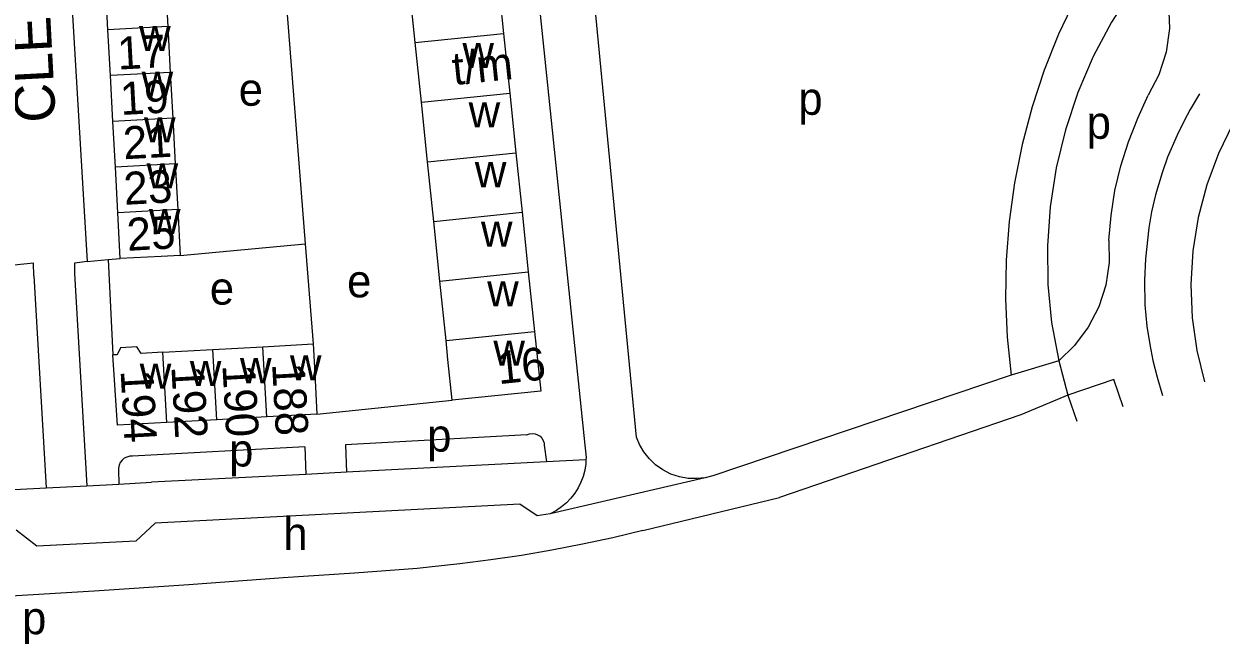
# Model space of a CAD drawing. Extents: x 161258 to 163262, y 380749 to 382054.
# Drawn here: x 162490.8 to 162637.4, y 380751.4 to 380827.3 of the extents above; entities that cross this region are included whole.
import ezdxf

# ---------------------------------------------------------------- set-up
doc = ezdxf.new("R2010")
doc.units = 0
for name, color, linetype in [('BLT_Basislijn', 7, 'Continuous'), ('BLT_Bebouwing', 7, 'Continuous'), ('BLT_Centroide', 7, 'Continuous'), ('BLT_Huisnummer', 7, 'Continuous'), ('BLT_Huisnummer_ tussenligend', 7, 'Continuous'), ('BLT_Huisnummer_reeks', 7, 'Continuous'), ('BLT_Onderverdeling_panden', 7, 'Continuous'), ('BLT_Straatnaam', 7, 'Continuous'), ('BLT_Vlakafsluiter', 7, 'Continuous')]:
    doc.layers.add(name, color=color, linetype=linetype)

msp = doc.modelspace()

# ---------------------------------------------------------------- linework, layer by layer
at = {"layer": 'BLT_Basislijn'}
for p, q in [((162521.15, 380853.1), (162525.29, 380800.38)), ((162565.87, 380776.71), (162560.55, 380831.67)), ((162509.99, 380798.96), (162525.29, 380800.38)), ((162525.29, 380800.38), (162526.26, 380788.12)), ((162498.58, 380798.22), (162501.17, 380798.44)), ((162501.17, 380798.44), (162502.65, 380798.57)), ((162501.17, 380798.44), (162501.73, 380786.77)), ((162492.07, 380796.45), (162493.57, 380770.5)), ((162497.06, 380796.74), (162498.56, 380770.76)), ((162617.56, 380786.03), (162611.74, 380784.3)), ((162611.74, 380784.3), (162575.22, 380771.98)), ((162624.32, 380783.76), (162618.67, 380781.86)), ((162625.44, 380780.41), (162624.32, 380783.76)), ((162526.73, 380779.52), (162543.28, 380781.22)), ((162618.67, 380781.86), (162612.92, 380779.45)), ((162612.92, 380779.45), (162583.38, 380769.31)), ((162552.44, 380776.97), (162530.24, 380775.78)), ((162525.24, 380775.51), (162504.16, 380774.37)), ((162525.24, 380775.51), (162525.36, 380772.14)), ((162530.24, 380775.78), (162530.36, 380772.4)), ((162554.56, 380775.73), (162554.83, 380773.66)), ((162554.83, 380773.66), (162530.36, 380772.4)), ((162559.66, 380773.91), (162554.83, 380773.66)), ((162502.43, 380772.73), (162502.48, 380770.96)), ((162525.36, 380772.14), (162506.48, 380771.17)), ((162530.36, 380772.4), (162525.36, 380772.14)), ((162493.57, 380770.5), (162498.56, 380770.76)), ((162498.56, 380770.76), (162502.48, 380770.96)), ((162502.48, 380770.96), (162506.48, 380771.17)), ((162489.64, 380770.29), (162493.57, 380770.5)), ((162566.64, 380765.27), (162583.38, 380769.31))]:
    msp.add_line(p, q, dxfattribs=at)
for points in [[(162546.79, 380880.94), (162550.5, 380862.73), (162559.51, 380775.73)], [(162496.7, 380871.17), (162494.25, 380870.92), (162498.58, 380798.22)], [(162629.33, 380835.15), (162626.53, 380831.47), (162624.01, 380827.51), (162621.79, 380823.32), (162619.91, 380818.92), (162618.39, 380814.35), (162617.25, 380809.66), (162616.51, 380804.91), (162616.17, 380800.13), (162616.22, 380795.39), (162616.65, 380790.72), (162617.56, 380786.03)], [(162629.33, 380835.15), (162630.39, 380832.54), (162631.01, 380829.7), (162631.13, 380826.75), (162630.72, 380823.82), (162629.82, 380821.06), (162628.51, 380818.56)], [(162621.79, 380834.4), (162619.55, 380830.31), (162617.54, 380826.05), (162615.78, 380821.65), (162614.29, 380817.14), (162613.06, 380812.53), (162612.12, 380807.85), (162611.47, 380803.12), (162611.11, 380798.38), (162611.04, 380793.64), (162611.25, 380788.94), (162611.74, 380784.3)], [(162623.71, 380800.78), (162623.96, 380803.84), (162624.44, 380806.9), (162625.16, 380809.92), (162626.09, 380812.88), (162627.25, 380815.75), (162628.51, 380818.56)], [(162634.78, 380818.72), (162633.64, 380816.82), (162632.92, 380815.42), (162632.06, 380813.66), (162630.87, 380810.97), (162630.23, 380809.07), (162629.41, 380806.39), (162628.92, 380804.31), (162628.6, 380802.32), (162628.17, 380798.55), (162628.06, 380795.93), (162628.11, 380792.92), (162628.35, 380790.3), (162628.72, 380788.04), (162629.08, 380786.07), (162629.6, 380784.04), (162630.28, 380781.81)], [(162640.97, 380818.44), (162638.88, 380815.06), (162637.1, 380811.43), (162635.67, 380807.6), (162634.62, 380803.61), (162633.97, 380799.53), (162633.73, 380795.41), (162633.9, 380791.32), (162634.47, 380787.32), (162635.41, 380783.46)], [(162623.71, 380800.78), (162623.73, 380798.07), (162623.31, 380795.32), (162622.45, 380792.65), (162621.15, 380790.15), (162619.5, 380787.92), (162617.56, 380786.03)], [(162492.07, 380796.45), (162492, 380798.01), (162487.66, 380797.55)], [(162498.58, 380798.22), (162497.04, 380798.01), (162497.06, 380796.74)], [(162618.67, 380781.86), (162619.76, 380778.67)], [(162552.44, 380776.97), (162552.76, 380777.1), (162553.09, 380777.14), (162553.43, 380777.11), (162553.75, 380777), (162554.04, 380776.81), (162554.27, 380776.57), (162554.44, 380776.28), (162554.54, 380775.95), (162554.56, 380775.73)], [(162574.27, 380771.74), (162573.26, 380771.62), (162572.2, 380771.65), (162571.12, 380771.83), (162570.07, 380772.18), (162569.08, 380772.68), (162568.17, 380773.32), (162567.39, 380774.08), (162566.74, 380774.92), (162566.23, 380775.81), (162565.87, 380776.71)], [(162559.51, 380775.73), (162559.63, 380774.97), (162559.68, 380774.19), (162559.66, 380773.91)], [(162504.16, 380774.37), (162503.8, 380774.36), (162503.46, 380774.27), (162503.14, 380774.11), (162502.87, 380773.87), (162502.65, 380773.59), (162502.5, 380773.26), (162502.43, 380772.91), (162502.43, 380772.73)], [(162559.66, 380773.91), (162559.64, 380773.42), (162559.52, 380772.65), (162559.33, 380771.9), (162559.05, 380771.18), (162558.71, 380770.49), (162558.29, 380769.83), (162557.82, 380769.22), (162557.27, 380768.67), (162556.68, 380768.17), (162556.04, 380767.74), (162555.27, 380767.33)], [(162575.22, 380771.98), (162574.27, 380771.74)], [(162555.27, 380767.33), (162553.68, 380767.07), (162551.56, 380768.48), (162506.93, 380766.18), (162504.55, 380763.97), (162492.44, 380763.36), (162489.88, 380765.3)], [(162566.64, 380765.27), (162562.95, 380764.39), (162559.23, 380763.59), (162555.5, 380762.87), (162551.76, 380762.22), (162548, 380761.66), (162544.24, 380761.17), (162540.46, 380760.77), (162539.01, 380760.63)], [(162539.01, 380760.63), (162531.34, 380760.03), (162522.59, 380759.46)], [(162522.59, 380759.46), (162511.02, 380758.61), (162499.43, 380757.84), (162487.84, 380757.14), (162481.88, 380756.82)]]:
    msp.add_lwpolyline(points, dxfattribs=at)
at = {"layer": 'BLT_Bebouwing'}
for p, q in [((162501.13, 380826.57), (162500.82, 380832.17)), ((162508.16, 380832.57), (162508.46, 380826.97)), ((162538.77, 380825.01), (162538.01, 380832.31)), ((162548.81, 380833.42), (162549.57, 380826.12)), ((162501.43, 380820.97), (162501.13, 380826.57)), ((162508.46, 380826.97), (162508.77, 380821.37)), ((162539.52, 380817.71), (162538.77, 380825.01)), ((162549.57, 380826.12), (162550.33, 380818.83)), ((162501.73, 380815.37), (162501.43, 380820.97)), ((162508.77, 380821.37), (162509.07, 380815.77)), ((162540.27, 380810.41), (162539.52, 380817.71)), ((162550.33, 380818.83), (162551.09, 380811.53)), ((162502.04, 380809.77), (162501.73, 380815.37)), ((162509.07, 380815.77), (162509.38, 380810.17)), ((162509.38, 380810.17), (162509.68, 380804.56)), ((162541.02, 380803.12), (162540.27, 380810.41)), ((162551.09, 380811.53), (162551.85, 380804.23)), ((162502.34, 380804.17), (162502.04, 380809.77)), ((162509.68, 380804.56), (162509.99, 380798.96)), ((162502.65, 380798.57), (162502.34, 380804.17)), ((162541.77, 380795.82), (162541.02, 380803.12)), ((162551.85, 380804.23), (162552.61, 380796.93)), ((162552.61, 380796.93), (162553.37, 380789.64)), ((162542.53, 380788.52), (162541.77, 380795.82)), ((162553.37, 380789.64), (162554.13, 380782.34)), ((162520.12, 380787.78), (162526.26, 380788.12)), ((162502.29, 380778.17), (162501.73, 380786.77)), ((162507.86, 380787.11), (162513.99, 380787.45)), ((162513.99, 380787.45), (162520.12, 380787.78)), ((162554.13, 380782.34), (162543.28, 380781.22)), ((162526.73, 380779.52), (162520.6, 380779.18)), ((162508.33, 380778.5), (162502.29, 380778.17)), ((162514.47, 380778.84), (162508.33, 380778.5)), ((162520.6, 380779.18), (162514.47, 380778.84))]:
    msp.add_line(p, q, dxfattribs=at)
for points in [[(162509.99, 380798.96), (162507.64, 380798.84), (162502.65, 380798.57)], [(162526.26, 380788.12), (162526.45, 380784.51), (162526.73, 380779.52)], [(162543.28, 380781.22), (162542.77, 380786.19), (162542.53, 380788.52)], [(162507.86, 380787.11), (162505.22, 380786.96), (162504.67, 380787.75), (162502.69, 380787.65), (162502.28, 380786.8), (162501.73, 380786.77)]]:
    msp.add_lwpolyline(points, dxfattribs=at)
at = {"layer": 'BLT_Onderverdeling_panden'}
for p, q in [((162508.46, 380826.97), (162501.13, 380826.57)), ((162538.77, 380825.01), (162549.57, 380826.12)), ((162508.77, 380821.37), (162501.43, 380820.97)), ((162539.52, 380817.71), (162550.33, 380818.83)), ((162509.07, 380815.77), (162501.73, 380815.37)), ((162509.38, 380810.17), (162502.04, 380809.77)), ((162540.27, 380810.41), (162551.09, 380811.53)), ((162509.68, 380804.56), (162502.34, 380804.17)), ((162541.02, 380803.12), (162551.85, 380804.23)), ((162541.77, 380795.82), (162552.61, 380796.93)), ((162542.53, 380788.52), (162553.37, 380789.64)), ((162508.33, 380778.5), (162507.86, 380787.11)), ((162514.47, 380778.84), (162513.99, 380787.45)), ((162520.6, 380779.18), (162520.12, 380787.78))]:
    msp.add_line(p, q, dxfattribs=at)
at = {"layer": 'BLT_Vlakafsluiter'}
for p, q in [((162617.56, 380786.03), (162618.67, 380781.86)), ((162574.27, 380771.74), (162555.27, 380767.33))]:
    msp.add_line(p, q, dxfattribs=at)

# ---------------------------------------------------------------- texts
at = {"layer": 'BLT_Centroide'}
for s, p in [('w', (162504.95, 380823.97)), ('w', (162544.54, 380821.91)), ('w', (162505.26, 380818.38)), ('e', (162517.15, 380817.28)), ('p', (162585.67, 380816.17)), ('w', (162545.3, 380814.62)), ('p', (162620.97, 380813.23)), ('w', (162505.55, 380812.78)), ('w', (162505.87, 380807.16)), ('w', (162546.06, 380807.31)), ('w', (162506.16, 380801.56)), ('w', (162546.81, 380800.03)), ('e', (162530.42, 380793.82)), ('e', (162513.61, 380792.93)), ('w', (162547.57, 380792.72)), ('w', (162548.33, 380785.44)), ('w', (162523.42, 380783.66)), ('w', (162505.03, 380782.62)), ('w', (162511.16, 380782.97)), ('w', (162517.3, 380783.31)), ('p', (162540.22, 380774.93)), ('p', (162515.97, 380773.11)), ('h', (162522.61, 380762.9)), ('p', (162490.62, 380752.57))]:
    msp.add_text(s, height=4, dxfattribs=at).set_placement(p)
at = {"layer": 'BLT_Huisnummer'}
for s, rotation, p in [('17', 3.1115, (162502.38, 380821.7)), ('21', 3.1115, (162503.09, 380810.72)), ('25', 3.1067, (162503.55, 380799.51)), ('188', 273.161, (162521.23, 380785.69)), ('194', 273.1595, (162502.68, 380784.85))]:
    msp.add_text(s, height=4, rotation=rotation, dxfattribs=at).set_placement(p)
at = {"layer": 'BLT_Huisnummer_ tussenligend'}
for s, rotation, p in [('19', 3.1115, (162502.73, 380816.14)), ('23', 3.1115, (162503.16, 380805.14)), ('190', 273.161, (162515.15, 380785.52)), ('192', 273.161, (162508.9, 380785.34))]:
    msp.add_text(s, height=4, rotation=rotation, dxfattribs=at).set_placement(p)
at = {"layer": 'BLT_Huisnummer_reeks'}
for s, rotation, p in [('t/m', 5.887, (162543.49, 380819.8)), ('16', 5.8836, (162548.98, 380783.18))]:
    msp.add_text(s, height=4, rotation=rotation, dxfattribs=at).set_placement(p)
at = {"layer": 'BLT_Straatnaam'}
msp.add_text('CLEMATISSTRAAT', height=5, rotation=92.9642, dxfattribs=at).set_placement((162494.75, 380815.34))

doc.saveas('drawing.dxf')
